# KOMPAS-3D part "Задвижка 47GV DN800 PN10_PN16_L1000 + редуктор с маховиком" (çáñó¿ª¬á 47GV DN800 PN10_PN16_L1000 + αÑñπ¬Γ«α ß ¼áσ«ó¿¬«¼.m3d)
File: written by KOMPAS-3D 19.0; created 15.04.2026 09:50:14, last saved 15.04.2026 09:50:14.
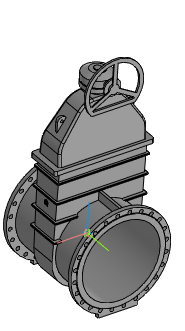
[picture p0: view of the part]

Document properties: Автор: Энергия; Полное имя файла: ..\Задвижка 47GV DN800 PN10_PN16_L1000 + редуктор с маховиком.a3d

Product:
- Part/product: Задвижка 47GV DN800 PN10_PN16_L1000 + редуктор с маховиком
    Масса: 2872.28

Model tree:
1. Операция без истории:1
